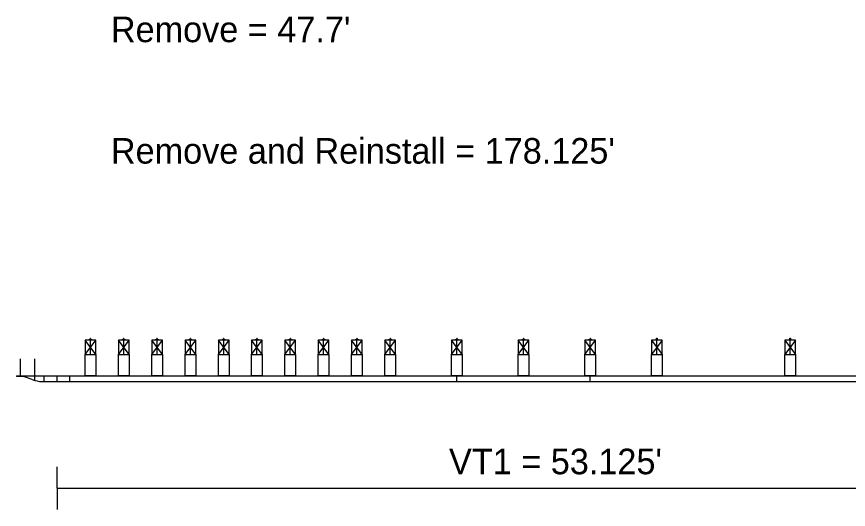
# Model space of a CAD drawing. Extents: x 16537443 to 16538473, y 7054586 to 7055469.
# Drawn here: x 16538170.48 to 16538209.48, y 7055445.95 to 7055469.08 of the extents above; entities that cross this region are included whole.
import ezdxf

# ---------------------------------------------------------------- set-up
doc = ezdxf.new("R2010")
doc.units = 0
doc.layers.add('Draft_DNC', color=7, linetype='Continuous')

msp = doc.modelspace()

# ---------------------------------------------------------------- linework, layer by layer
at = {"layer": 'Draft_DNC'}
for p, q in [((16538174.19, 7055453.224), (16538173.69, 7055453.891)), ((16538173.69, 7055453.224), (16538174.19, 7055453.891)), ((16538174.19, 7055453.891), (16538173.69, 7055453.891)), ((16538173.86, 7055453.891), (16538173.86, 7055453.907)), ((16538174.02, 7055453.907), (16538173.86, 7055453.907)), ((16538173.9, 7055453.907), (16538173.9, 7055453.945)), ((16538173.98, 7055453.945), (16538173.9, 7055453.945)), ((16538173.916, 7055453.907), (16538173.916, 7055453.945)), ((16538173.93, 7055453.945), (16538173.93, 7055453.974)), ((16538173.95, 7055453.974), (16538173.93, 7055453.974)), ((16538173.94, 7055453.224), (16538173.94, 7055453.891)), ((16538173.95, 7055453.945), (16538173.95, 7055453.974)), ((16538173.964, 7055453.907), (16538173.964, 7055453.945)), ((16538173.98, 7055453.907), (16538173.98, 7055453.945)), ((16538174.02, 7055453.891), (16538174.02, 7055453.907)), ((16538175.752, 7055453.224), (16538175.252, 7055453.891)), ((16538175.252, 7055453.224), (16538175.752, 7055453.891)), ((16538175.752, 7055453.891), (16538175.252, 7055453.891)), ((16538175.422, 7055453.891), (16538175.422, 7055453.907)), ((16538175.582, 7055453.907), (16538175.422, 7055453.907)), ((16538175.462, 7055453.907), (16538175.462, 7055453.945)), ((16538175.542, 7055453.945), (16538175.462, 7055453.945)), ((16538175.478, 7055453.907), (16538175.478, 7055453.945)), ((16538175.492, 7055453.945), (16538175.492, 7055453.974)), ((16538175.512, 7055453.974), (16538175.492, 7055453.974)), ((16538175.502, 7055453.224), (16538175.502, 7055453.891)), ((16538175.512, 7055453.945), (16538175.512, 7055453.974)), ((16538175.526, 7055453.907), (16538175.526, 7055453.945)), ((16538175.542, 7055453.907), (16538175.542, 7055453.945)), ((16538175.582, 7055453.891), (16538175.582, 7055453.907)), ((16538177.315, 7055453.224), (16538176.815, 7055453.891)), ((16538176.815, 7055453.224), (16538177.315, 7055453.891)), ((16538177.315, 7055453.891), (16538176.815, 7055453.891)), ((16538176.985, 7055453.891), (16538176.985, 7055453.907)), ((16538177.145, 7055453.907), (16538176.985, 7055453.907)), ((16538177.025, 7055453.907), (16538177.025, 7055453.945)), ((16538177.105, 7055453.945), (16538177.025, 7055453.945)), ((16538177.041, 7055453.907), (16538177.041, 7055453.945)), ((16538177.055, 7055453.945), (16538177.055, 7055453.974)), ((16538177.075, 7055453.974), (16538177.055, 7055453.974)), ((16538177.065, 7055453.224), (16538177.065, 7055453.891)), ((16538177.075, 7055453.945), (16538177.075, 7055453.974)), ((16538177.089, 7055453.907), (16538177.089, 7055453.945)), ((16538177.105, 7055453.907), (16538177.105, 7055453.945)), ((16538177.145, 7055453.891), (16538177.145, 7055453.907)), ((16538178.877, 7055453.224), (16538178.377, 7055453.891)), ((16538178.377, 7055453.224), (16538178.877, 7055453.891)), ((16538178.877, 7055453.891), (16538178.377, 7055453.891)), ((16538178.547, 7055453.891), (16538178.547, 7055453.907)), ((16538178.707, 7055453.907), (16538178.547, 7055453.907)), ((16538178.587, 7055453.907), (16538178.587, 7055453.945)), ((16538178.667, 7055453.945), (16538178.587, 7055453.945)), ((16538178.603, 7055453.907), (16538178.603, 7055453.945)), ((16538178.617, 7055453.945), (16538178.617, 7055453.974)), ((16538178.637, 7055453.974), (16538178.617, 7055453.974)), ((16538178.627, 7055453.224), (16538178.627, 7055453.891)), ((16538178.637, 7055453.945), (16538178.637, 7055453.974)), ((16538178.651, 7055453.907), (16538178.651, 7055453.945)), ((16538178.667, 7055453.907), (16538178.667, 7055453.945)), ((16538178.707, 7055453.891), (16538178.707, 7055453.907)), ((16538180.44, 7055453.224), (16538179.94, 7055453.891)), ((16538179.94, 7055453.224), (16538180.44, 7055453.891)), ((16538180.44, 7055453.891), (16538179.94, 7055453.891)), ((16538180.11, 7055453.891), (16538180.11, 7055453.907)), ((16538180.27, 7055453.907), (16538180.11, 7055453.907)), ((16538180.15, 7055453.907), (16538180.15, 7055453.945)), ((16538180.23, 7055453.945), (16538180.15, 7055453.945)), ((16538180.166, 7055453.907), (16538180.166, 7055453.945)), ((16538180.18, 7055453.945), (16538180.18, 7055453.974)), ((16538180.2, 7055453.974), (16538180.18, 7055453.974)), ((16538180.19, 7055453.224), (16538180.19, 7055453.891)), ((16538180.2, 7055453.945), (16538180.2, 7055453.974)), ((16538180.214, 7055453.907), (16538180.214, 7055453.945)), ((16538180.23, 7055453.907), (16538180.23, 7055453.945)), ((16538180.27, 7055453.891), (16538180.27, 7055453.907)), ((16538182.002, 7055453.224), (16538181.502, 7055453.891)), ((16538181.502, 7055453.224), (16538182.002, 7055453.891)), ((16538182.002, 7055453.891), (16538181.502, 7055453.891)), ((16538181.672, 7055453.891), (16538181.672, 7055453.907)), ((16538181.832, 7055453.907), (16538181.672, 7055453.907)), ((16538181.712, 7055453.907), (16538181.712, 7055453.945)), ((16538181.792, 7055453.945), (16538181.712, 7055453.945)), ((16538181.728, 7055453.907), (16538181.728, 7055453.945)), ((16538181.742, 7055453.945), (16538181.742, 7055453.974)), ((16538181.762, 7055453.974), (16538181.742, 7055453.974)), ((16538181.752, 7055453.224), (16538181.752, 7055453.891)), ((16538181.762, 7055453.945), (16538181.762, 7055453.974)), ((16538181.776, 7055453.907), (16538181.776, 7055453.945)), ((16538181.792, 7055453.907), (16538181.792, 7055453.945)), ((16538181.832, 7055453.891), (16538181.832, 7055453.907)), ((16538183.565, 7055453.224), (16538183.065, 7055453.891)), ((16538183.065, 7055453.224), (16538183.565, 7055453.891)), ((16538183.565, 7055453.891), (16538183.065, 7055453.891)), ((16538183.235, 7055453.891), (16538183.235, 7055453.907)), ((16538183.395, 7055453.907), (16538183.235, 7055453.907)), ((16538183.275, 7055453.907), (16538183.275, 7055453.945)), ((16538183.355, 7055453.945), (16538183.275, 7055453.945)), ((16538183.291, 7055453.907), (16538183.291, 7055453.945)), ((16538183.305, 7055453.945), (16538183.305, 7055453.974)), ((16538183.325, 7055453.974), (16538183.305, 7055453.974)), ((16538183.315, 7055453.224), (16538183.315, 7055453.891)), ((16538183.325, 7055453.945), (16538183.325, 7055453.974)), ((16538183.339, 7055453.907), (16538183.339, 7055453.945)), ((16538183.355, 7055453.907), (16538183.355, 7055453.945)), ((16538183.395, 7055453.891), (16538183.395, 7055453.907)), ((16538185.127, 7055453.224), (16538184.627, 7055453.891)), ((16538184.627, 7055453.224), (16538185.127, 7055453.891)), ((16538185.127, 7055453.891), (16538184.627, 7055453.891)), ((16538184.797, 7055453.891), (16538184.797, 7055453.907)), ((16538184.957, 7055453.907), (16538184.797, 7055453.907)), ((16538184.837, 7055453.907), (16538184.837, 7055453.945)), ((16538184.917, 7055453.945), (16538184.837, 7055453.945)), ((16538184.853, 7055453.907), (16538184.853, 7055453.945)), ((16538184.867, 7055453.945), (16538184.867, 7055453.974)), ((16538184.887, 7055453.974), (16538184.867, 7055453.974)), ((16538184.877, 7055453.224), (16538184.877, 7055453.891)), ((16538184.887, 7055453.945), (16538184.887, 7055453.974)), ((16538184.901, 7055453.907), (16538184.901, 7055453.945)), ((16538184.917, 7055453.907), (16538184.917, 7055453.945)), ((16538184.957, 7055453.891), (16538184.957, 7055453.907)), ((16538186.69, 7055453.224), (16538186.19, 7055453.891)), ((16538186.19, 7055453.224), (16538186.69, 7055453.891)), ((16538186.69, 7055453.891), (16538186.19, 7055453.891)), ((16538186.36, 7055453.891), (16538186.36, 7055453.907)), ((16538186.52, 7055453.907), (16538186.36, 7055453.907)), ((16538186.4, 7055453.907), (16538186.4, 7055453.945)), ((16538186.48, 7055453.945), (16538186.4, 7055453.945)), ((16538186.416, 7055453.907), (16538186.416, 7055453.945)), ((16538186.43, 7055453.945), (16538186.43, 7055453.974)), ((16538186.45, 7055453.974), (16538186.43, 7055453.974)), ((16538186.44, 7055453.224), (16538186.44, 7055453.891)), ((16538186.45, 7055453.945), (16538186.45, 7055453.974)), ((16538186.464, 7055453.907), (16538186.464, 7055453.945)), ((16538186.48, 7055453.907), (16538186.48, 7055453.945)), ((16538186.52, 7055453.891), (16538186.52, 7055453.907)), ((16538188.252, 7055453.224), (16538187.752, 7055453.891)), ((16538187.752, 7055453.224), (16538188.252, 7055453.891)), ((16538188.252, 7055453.891), (16538187.752, 7055453.891)), ((16538187.922, 7055453.891), (16538187.922, 7055453.907)), ((16538188.082, 7055453.907), (16538187.922, 7055453.907)), ((16538187.962, 7055453.907), (16538187.962, 7055453.945)), ((16538188.042, 7055453.945), (16538187.962, 7055453.945)), ((16538187.978, 7055453.907), (16538187.978, 7055453.945)), ((16538187.992, 7055453.945), (16538187.992, 7055453.974)), ((16538188.012, 7055453.974), (16538187.992, 7055453.974)), ((16538188.002, 7055453.224), (16538188.002, 7055453.891)), ((16538188.012, 7055453.945), (16538188.012, 7055453.974)), ((16538188.026, 7055453.907), (16538188.026, 7055453.945)), ((16538188.042, 7055453.907), (16538188.042, 7055453.945)), ((16538188.082, 7055453.891), (16538188.082, 7055453.907)), ((16538191.377, 7055453.224), (16538190.877, 7055453.891)), ((16538190.877, 7055453.224), (16538191.377, 7055453.891)), ((16538191.377, 7055453.891), (16538190.877, 7055453.891)), ((16538191.047, 7055453.891), (16538191.047, 7055453.907)), ((16538191.207, 7055453.907), (16538191.047, 7055453.907)), ((16538191.087, 7055453.907), (16538191.087, 7055453.945)), ((16538191.167, 7055453.945), (16538191.087, 7055453.945)), ((16538191.103, 7055453.907), (16538191.103, 7055453.945)), ((16538191.117, 7055453.945), (16538191.117, 7055453.974)), ((16538191.137, 7055453.974), (16538191.117, 7055453.974)), ((16538191.127, 7055453.224), (16538191.127, 7055453.891)), ((16538191.137, 7055453.945), (16538191.137, 7055453.974)), ((16538191.151, 7055453.907), (16538191.151, 7055453.945)), ((16538191.167, 7055453.907), (16538191.167, 7055453.945)), ((16538191.207, 7055453.891), (16538191.207, 7055453.907)), ((16538194.502, 7055453.224), (16538194.002, 7055453.891)), ((16538194.002, 7055453.224), (16538194.502, 7055453.891)), ((16538194.502, 7055453.891), (16538194.002, 7055453.891)), ((16538194.172, 7055453.891), (16538194.172, 7055453.907)), ((16538194.332, 7055453.907), (16538194.172, 7055453.907)), ((16538194.212, 7055453.907), (16538194.212, 7055453.945)), ((16538194.292, 7055453.945), (16538194.212, 7055453.945)), ((16538194.228, 7055453.907), (16538194.228, 7055453.945)), ((16538194.242, 7055453.945), (16538194.242, 7055453.974)), ((16538194.262, 7055453.974), (16538194.242, 7055453.974)), ((16538194.252, 7055453.224), (16538194.252, 7055453.891)), ((16538194.262, 7055453.945), (16538194.262, 7055453.974)), ((16538194.276, 7055453.907), (16538194.276, 7055453.945)), ((16538194.292, 7055453.907), (16538194.292, 7055453.945)), ((16538194.332, 7055453.891), (16538194.332, 7055453.907)), ((16538197.627, 7055453.224), (16538197.127, 7055453.891)), ((16538197.127, 7055453.224), (16538197.627, 7055453.891)), ((16538197.627, 7055453.891), (16538197.127, 7055453.891)), ((16538197.297, 7055453.891), (16538197.297, 7055453.907)), ((16538197.457, 7055453.907), (16538197.297, 7055453.907)), ((16538197.337, 7055453.907), (16538197.337, 7055453.945)), ((16538197.417, 7055453.945), (16538197.337, 7055453.945)), ((16538197.353, 7055453.907), (16538197.353, 7055453.945)), ((16538197.367, 7055453.945), (16538197.367, 7055453.974)), ((16538197.387, 7055453.974), (16538197.367, 7055453.974)), ((16538197.377, 7055453.224), (16538197.377, 7055453.891)), ((16538197.387, 7055453.945), (16538197.387, 7055453.974)), ((16538197.401, 7055453.907), (16538197.401, 7055453.945)), ((16538197.417, 7055453.907), (16538197.417, 7055453.945)), ((16538197.457, 7055453.891), (16538197.457, 7055453.907)), ((16538200.252, 7055453.892), (16538200.752, 7055453.225)), ((16538200.752, 7055453.892), (16538200.252, 7055453.225)), ((16538200.502, 7055453.989), (16538200.502, 7055453.996)), ((16538200.502, 7055453.225), (16538200.502, 7055453.892)), ((16538206.502, 7055453.892), (16538207.002, 7055453.225)), ((16538207.002, 7055453.892), (16538206.502, 7055453.225)), ((16538206.752, 7055453.989), (16538206.752, 7055453.996)), ((16538206.752, 7055453.225), (16538206.752, 7055453.892)), ((16538170.648, 7055453.016), (16538170.648, 7055452.198)), ((16538171.315, 7055453.016), (16538171.315, 7055452.014)), ((16538173.69, 7055453.224), (16538174.19, 7055453.224)), ((16538173.69, 7055452.225), (16538173.69, 7055453.224)), ((16538174.19, 7055453.224), (16538174.19, 7055452.225)), ((16538175.252, 7055453.224), (16538175.752, 7055453.224)), ((16538175.252, 7055452.225), (16538175.252, 7055453.224)), ((16538175.752, 7055453.224), (16538175.752, 7055452.225)), ((16538176.815, 7055453.224), (16538177.315, 7055453.224)), ((16538176.815, 7055452.225), (16538176.815, 7055453.224)), ((16538177.315, 7055453.224), (16538177.315, 7055452.225)), ((16538178.377, 7055453.224), (16538178.877, 7055453.224)), ((16538178.377, 7055452.225), (16538178.377, 7055453.224)), ((16538178.877, 7055453.224), (16538178.877, 7055452.225)), ((16538179.94, 7055453.224), (16538180.44, 7055453.224)), ((16538179.94, 7055452.225), (16538179.94, 7055453.224)), ((16538180.44, 7055453.224), (16538180.44, 7055452.225)), ((16538181.502, 7055453.224), (16538182.002, 7055453.224)), ((16538181.502, 7055452.225), (16538181.502, 7055453.224)), ((16538182.002, 7055453.224), (16538182.002, 7055452.225)), ((16538183.065, 7055453.224), (16538183.565, 7055453.224)), ((16538183.065, 7055452.225), (16538183.065, 7055453.224)), ((16538183.565, 7055453.224), (16538183.565, 7055452.225)), ((16538184.627, 7055453.224), (16538185.127, 7055453.224)), ((16538184.627, 7055452.225), (16538184.627, 7055453.224)), ((16538184.627, 7055453.224), (16538185.127, 7055453.224)), ((16538184.627, 7055452.225), (16538184.627, 7055453.224)), ((16538185.127, 7055453.224), (16538185.127, 7055452.225)), ((16538185.127, 7055453.224), (16538185.127, 7055452.225)), ((16538186.19, 7055453.224), (16538186.69, 7055453.224)), ((16538186.19, 7055452.225), (16538186.19, 7055453.224)), ((16538186.69, 7055453.224), (16538186.69, 7055452.225)), ((16538187.752, 7055453.224), (16538188.252, 7055453.224)), ((16538187.752, 7055452.225), (16538187.752, 7055453.224)), ((16538188.252, 7055453.224), (16538188.252, 7055452.225)), ((16538190.877, 7055453.224), (16538191.377, 7055453.224)), ((16538190.877, 7055452.225), (16538190.877, 7055453.224)), ((16538191.377, 7055453.224), (16538191.377, 7055452.225)), ((16538194.002, 7055453.224), (16538194.502, 7055453.224)), ((16538194.002, 7055452.225), (16538194.002, 7055453.224)), ((16538194.502, 7055453.224), (16538194.502, 7055452.225)), ((16538197.127, 7055453.224), (16538197.627, 7055453.224)), ((16538197.127, 7055452.225), (16538197.127, 7055453.224)), ((16538197.627, 7055453.224), (16538197.627, 7055452.225)), ((16538200.252, 7055453.225), (16538200.752, 7055453.225)), ((16538200.252, 7055452.225), (16538200.252, 7055453.225)), ((16538200.752, 7055453.225), (16538200.752, 7055452.225)), ((16538206.502, 7055453.225), (16538207.002, 7055453.225)), ((16538206.502, 7055452.225), (16538206.502, 7055453.225)), ((16538207.002, 7055453.225), (16538207.002, 7055452.225)), ((16538170.481, 7055452.225), (16538170.481, 7055452.199)), ((16538170.481, 7055452.225), (16538209.877, 7055452.225)), ((16538170.731, 7055452.199), (16538170.481, 7055452.199)), ((16538171.773, 7055451.954), (16538171.773, 7055452.225)), ((16538172.377, 7055451.954), (16538172.377, 7055452.225)), ((16538172.981, 7055451.954), (16538172.981, 7055452.225)), ((16538174.19, 7055452.225), (16538173.69, 7055452.225)), ((16538175.752, 7055452.225), (16538175.252, 7055452.225)), ((16538177.315, 7055452.225), (16538176.815, 7055452.225)), ((16538178.877, 7055452.225), (16538178.377, 7055452.225)), ((16538180.44, 7055452.225), (16538179.94, 7055452.225)), ((16538182.002, 7055452.225), (16538181.502, 7055452.225)), ((16538183.565, 7055452.225), (16538183.065, 7055452.225)), ((16538185.127, 7055452.225), (16538184.627, 7055452.225)), ((16538185.127, 7055452.225), (16538184.627, 7055452.225)), ((16538186.69, 7055452.225), (16538186.19, 7055452.225)), ((16538188.252, 7055452.225), (16538187.752, 7055452.225)), ((16538191.377, 7055452.225), (16538190.877, 7055452.225)), ((16538191.127, 7055451.954), (16538191.127, 7055452.225)), ((16538194.502, 7055452.225), (16538194.002, 7055452.225)), ((16538197.627, 7055452.225), (16538197.127, 7055452.225)), ((16538197.377, 7055451.954), (16538197.377, 7055452.225)), ((16538200.752, 7055452.225), (16538200.252, 7055452.225)), ((16538207.002, 7055452.225), (16538206.502, 7055452.225)), ((16538171.215, 7055452.047), (16538171.072, 7055452.103)), ((16538171.677, 7055451.954), (16538209.877, 7055451.954)), ((16538171.773, 7055451.954), (16538197.377, 7055451.954)), ((16538172.377, 7055446.954), (16538172.377, 7055447.954)), ((16538172.377, 7055446.954), (16538225.502, 7055446.955)), ((16538172.377, 7055446.954), (16538172.377, 7055445.954))]:
    msp.add_line(p, q, dxfattribs=at)
for points in [[(16538173.69, 7055453.224), (16538174.19, 7055453.224), (16538174.19, 7055453.891), (16538173.69, 7055453.891)], [(16538175.252, 7055453.224), (16538175.752, 7055453.224), (16538175.752, 7055453.891), (16538175.252, 7055453.891)], [(16538176.815, 7055453.224), (16538177.315, 7055453.224), (16538177.315, 7055453.891), (16538176.815, 7055453.891)], [(16538178.377, 7055453.224), (16538178.877, 7055453.224), (16538178.877, 7055453.891), (16538178.377, 7055453.891)], [(16538179.94, 7055453.224), (16538180.44, 7055453.224), (16538180.44, 7055453.891), (16538179.94, 7055453.891)], [(16538181.502, 7055453.224), (16538182.002, 7055453.224), (16538182.002, 7055453.891), (16538181.502, 7055453.891)], [(16538183.065, 7055453.224), (16538183.565, 7055453.224), (16538183.565, 7055453.891), (16538183.065, 7055453.891)], [(16538184.627, 7055453.224), (16538185.127, 7055453.224), (16538185.127, 7055453.891), (16538184.627, 7055453.891)], [(16538186.19, 7055453.224), (16538186.69, 7055453.224), (16538186.69, 7055453.891), (16538186.19, 7055453.891)], [(16538187.752, 7055453.224), (16538188.252, 7055453.224), (16538188.252, 7055453.891), (16538187.752, 7055453.891)], [(16538190.877, 7055453.224), (16538191.377, 7055453.224), (16538191.377, 7055453.891), (16538190.877, 7055453.891)], [(16538194.002, 7055453.224), (16538194.502, 7055453.224), (16538194.502, 7055453.891), (16538194.002, 7055453.891)], [(16538197.127, 7055453.224), (16538197.627, 7055453.224), (16538197.627, 7055453.891), (16538197.127, 7055453.891)], [(16538200.252, 7055453.225), (16538200.752, 7055453.225), (16538200.752, 7055453.892), (16538200.252, 7055453.892)], [(16538206.502, 7055453.225), (16538207.002, 7055453.225), (16538207.002, 7055453.892), (16538206.502, 7055453.892)]]:
    msp.add_lwpolyline(points, close=True, dxfattribs=at)
for points in [[(16538200.469, 7055453.892), (16538200.469, 7055453.935), (16538200.535, 7055453.935), (16538200.535, 7055453.892)], [(16538200.483, 7055453.935), (16538200.483, 7055453.989), (16538200.522, 7055453.989), (16538200.522, 7055453.935)], [(16538206.719, 7055453.892), (16538206.719, 7055453.935), (16538206.785, 7055453.935), (16538206.785, 7055453.892)], [(16538206.733, 7055453.935), (16538206.733, 7055453.989), (16538206.772, 7055453.989), (16538206.772, 7055453.935)]]:
    msp.add_lwpolyline(points, dxfattribs=at)
for centre, major_axis, start_param, end_param in [((16538170.519, 7055450.876), (-1.379, 0), 4.300427, 4.558114), ((16538171.756, 7055453.449), (1.542, 0), 4.353641, 4.660842)]:
    msp.add_ellipse(centre, major_axis=major_axis, ratio=0.97085, start_param=start_param, end_param=end_param, dxfattribs=at)

# ---------------------------------------------------------------- texts
for s, p in [("Remove = 47.7'", (16538174.901, 7055467.884)), ("Remove and Reinstall = 178.125'", (16538174.901, 7055462.184)), ("VT1 = 53.125'", (16538190.755, 7055447.603))]:
    msp.add_text(s, height=1.2, rotation=0.001, dxfattribs=at).set_placement(p)

doc.saveas('drawing.dxf')
